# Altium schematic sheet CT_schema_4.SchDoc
size 298 x 247 mm
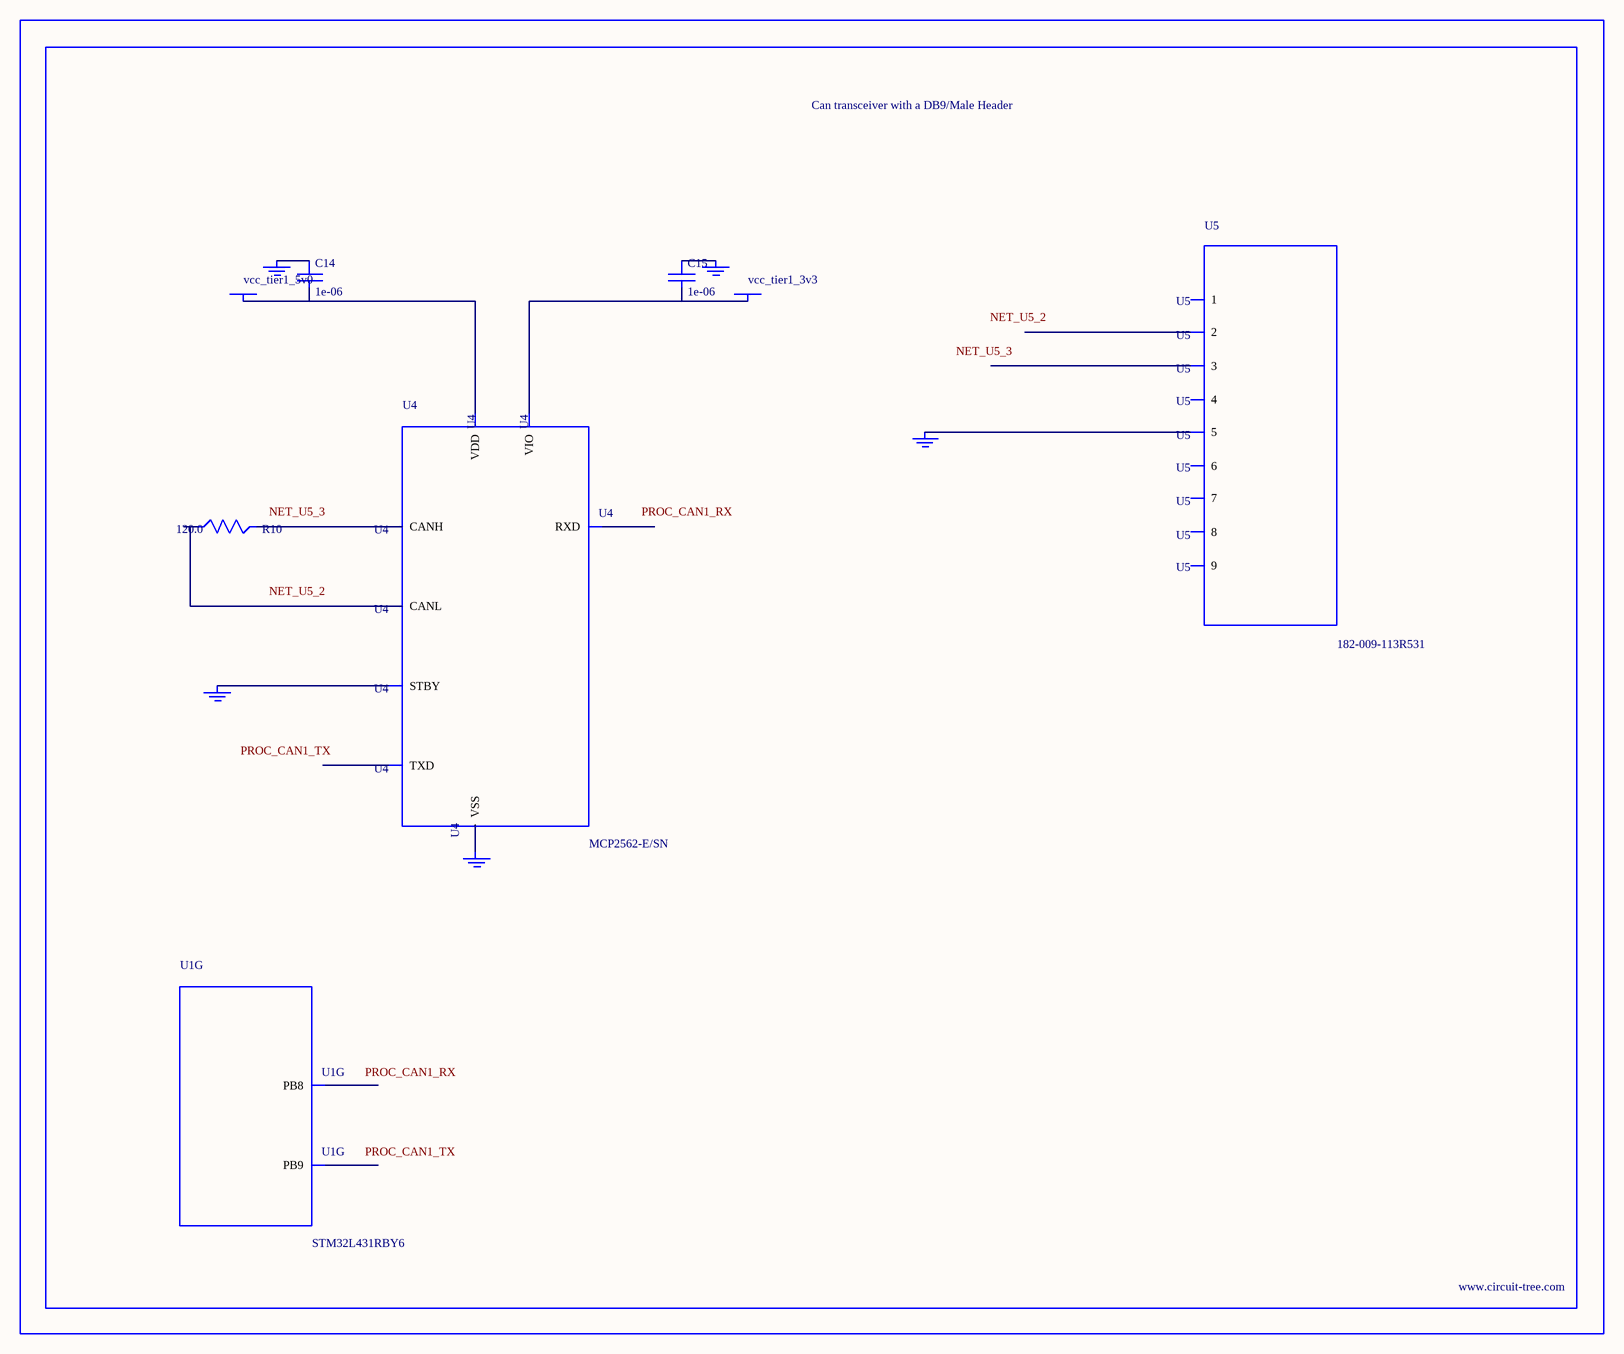
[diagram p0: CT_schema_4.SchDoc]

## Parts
BORDER3  (no value)
C14  1e-06  [C0603]
C15  1e-06  [C0603]
GND_INSTANCE_3_0  (no value)
GND_INSTANCE_3_1  (no value)
GND_INSTANCE_3_2  (no value)
GND_INSTANCE_3_3  (no value)
GND_INSTANCE_3_4  (no value)
POWER_INSTANCE_3_0  vcc_tier1_5v0
POWER_INSTANCE_3_1  vcc_tier1_3v3
R10  120.0  [R0603]
U1  STM32L431RBY6  [WLCSP64]  (part G of 7)
U4  MCP2562-E/SN  [SOIC-8]
U5  182-009-113R531  [182-009-MALE]

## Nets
NetC14_1: C14.1 GND_INSTANCE_3_0.0(GND)
NetC14_2: C14.2 POWER_INSTANCE_3_0.0(PWR) U4.3(VDD)
NetC15_1: C15.1 GND_INSTANCE_3_1.0(GND)
NetC15_2: C15.2 POWER_INSTANCE_3_1.0(PWR) U4.5(VIO)
NetGND_INSTANCE_3_2_0: GND_INSTANCE_3_2.0(GND) U4.8(STBY)
NetGND_INSTANCE_3_3_0: GND_INSTANCE_3_3.0(GND) U4.2(VSS)
NetGND_INSTANCE_3_4_0: GND_INSTANCE_3_4.0(GND) U5.5
NetR10_1: R10.1 U4.6(CANL)
NetR10_2: R10.2 U4.7(CANH)

Not connected (* = marked no-connect by the designer): U1 B6(PB9) C6(PB8); U4 1(TXD) 4(RXD); U5 1 2 3 4 6 7 8 9

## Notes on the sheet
- Labels drawn without touching a wire or pin: NET_U5_2, NET_U5_3, PROC_CAN1_RX, PROC_CAN1_TX

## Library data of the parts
BORDER3 = BORDER_PAGE3
C14 C15 = C0603C105K3RACTU
GND_INSTANCE_3_0-GND_INSTANCE_3_4 = GND
POWER_INSTANCE_3_0 POWER_INSTANCE_3_1 = PWR
R10 = RC0603JR-07120RL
